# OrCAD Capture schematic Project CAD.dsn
size A
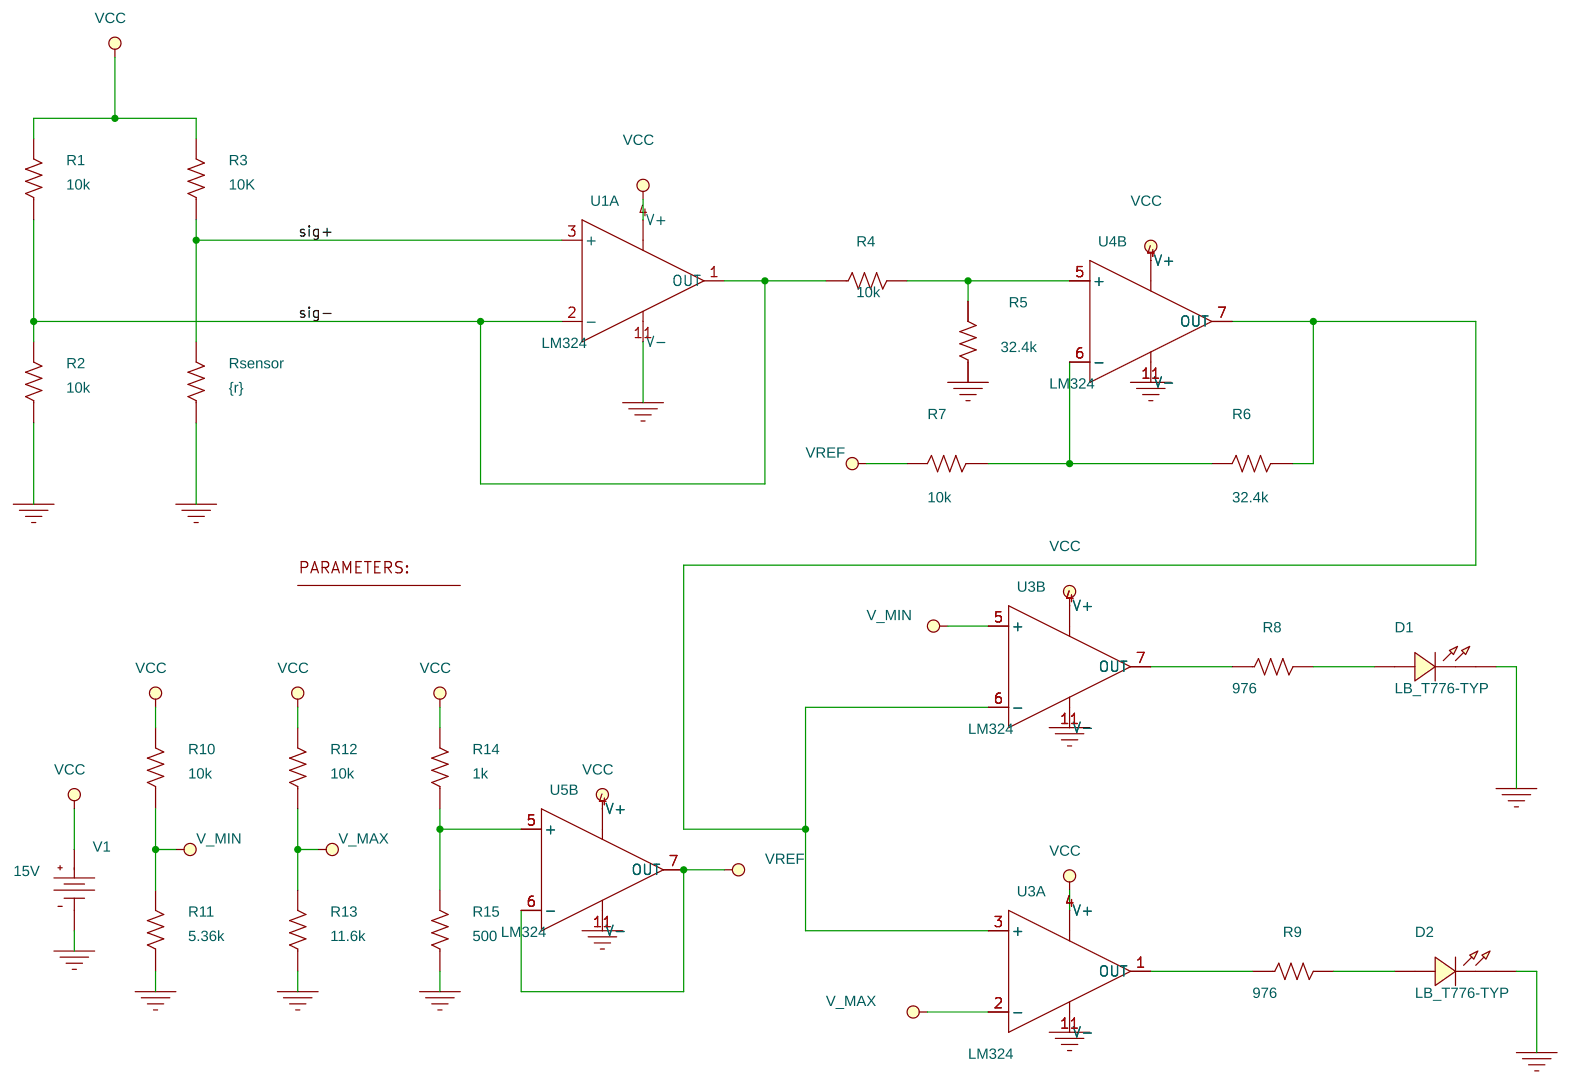
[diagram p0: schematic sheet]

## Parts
1  PARAM
D1  LB_T776-TYP
D2  LB_T776-TYP
R1  10k  [AXRC05]
R2  10k  [AXRC05]
R3  10K  [AXRC05]
R4  10k  [AXRC05]
R5  32.4k  [AXRC05]
R6  32.4k  [AXRC05]
R7  10k  [AXRC05]
R8  976  [AXRC05]
R9  976  [AXRC05]
R10  10k  [AXRC05]
R11  5.36k  [AXRC05]
R12  10k  [AXRC05]
R13  11.6k  [AXRC05]
R14  1k  [AXRC05]
R15  500  [AXRC05]
Rsensor  {r}  [AXRC05]
U1  LM324  [DIP10014W300L800]  (section A)
U3  LM324  [DIP10014W300L800]  (sections A,B)
U4  LM324  [DIP10014W300L800]  (section B)
U5  LM324  [DIP10014W300L800]  (section B)
V1  VDC

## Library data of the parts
1 = PARAM: r: 15k
D1 D2 = LB_T776-TYP
R1-R3 R8-R15 Rsensor = R: TOLERANCE: 1%
R4-R7 = R
U1 U3-U5 = LM324
V1 = VDC: DC: 15V

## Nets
VCC: R1.2 R3.2 R10.2 R12.2 R14.2 U1.4(V+) U3.4(V+) U4.4(V+) U5.4(V+) V1.0(+)
0: D1.2 D2.2 R2.1 R5.1 R11.1 R13.1 R15.1 Rsensor.1 U1.11(V-) U3.11(V-) U4.11(V-) U5.11(V-) V1.1(-)
sig+: R3.1 Rsensor.2 U1.3(+)
sig-: R1.1 R2.2 R4.1 U1.1(OUT) U1.2(-)
V_max: R12.1 R13.2 U3.2(-)
V_min: R10.1 R11.2 U3.5(+)
Vref: R7.2 U5.6(-) U5.7(OUT)
N18418: R6.1 U3.3(+) U3.6(-) U4.7(OUT)
N23968: D2.1 R9.2
N28880: D1.1 R8.2
N29104: R8.1 U3.7(OUT)
N30168: R9.1 U3.1(OUT)
N31426: R14.1 R15.2 U5.5(+)
N31874: R4.2 R5.2 U4.5(+)
N31909: R6.2 R7.1 U4.6(-)
